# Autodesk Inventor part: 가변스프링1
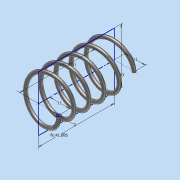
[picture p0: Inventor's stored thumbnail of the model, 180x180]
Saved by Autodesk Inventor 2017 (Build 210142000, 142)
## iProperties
Part Number: 가변스프링1
Material: 강철, 연강
Document SubType Name: Modeling
Designer: MRC
Density: 7.85 g/cm^3
Appearance: 반연마
Mass: 8.4366 g
Surface Area: 21.7438 cm^2
Volume: 1.07473 cm^3
Author: MRC
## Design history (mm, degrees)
sketch "스케치1"
  geometry: L1 (0, 0)-(0, 41.095); L2 (0, 41.095)-(11, 41.095); L3 (0, 0)-(11, 0); C1 r 1 at (11, 0)
  constraints: 6 end point, 2 horizontal, 1 centre point, 1 coincident, 1 vertical
  dimensions: "d0" = 41.0955 distance of L1.start L1.end (derived); "d1" = 11 distance of L1.end L2.end; "d2" = 11 distance of L1.start L3.end; "d3" = 2 diameter of C1
feature "코일1" sketch "스케치1" pitch "d4" = 10; turns "d6" = 5; dims "d5" = 41.0955 (= d0), "d7" = 0, angle "d8" = 90 deg, angle "d9" = 90 deg, "d10" = 0, "d11" = 0
sketch "스케치2"
  geometry: L1 (41.095, 15)-(0, 15); L2 (0, 15)-(0, -15); L3 (0, -15)-(41.095, -15); L4 (41.095, -15)-(41.095, 15); 2 further points
  constraints: 8 end point, 2 parallel, 1 coincident, 1 horizontal, 1 midpoint, 1 perpendicular
  dimensions: "d12" = 41.0955 distance of L2.end L3.end (= d0); "d13" = 30 distance of L3.end L1.start
extrude "돌출1" sketch "스케치2" stored distance "d14" = 0; taper "d15" = 0 deg
node "솔리드1"
